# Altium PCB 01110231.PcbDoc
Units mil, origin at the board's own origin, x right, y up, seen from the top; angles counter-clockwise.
Board outline 3350 x 4325 mil, 2 copper layers (Top Layer, Bottom Layer); 144 components, 62 nets, 316 pads, 13 vias.
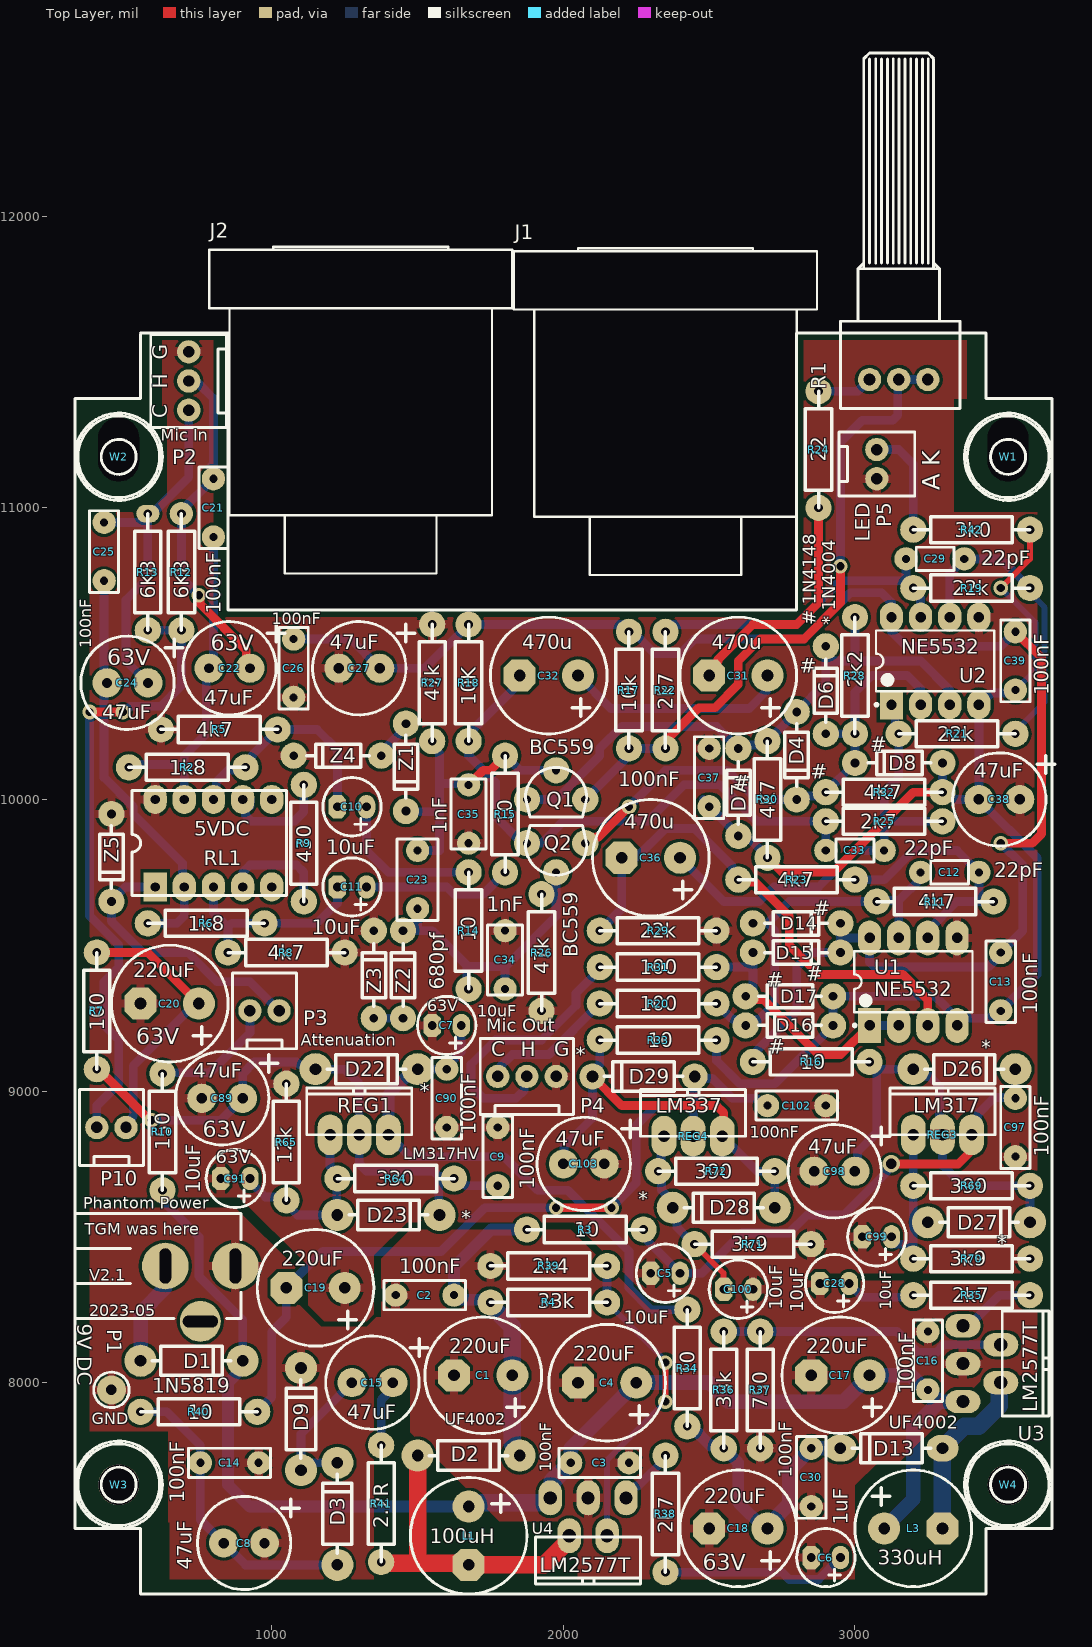
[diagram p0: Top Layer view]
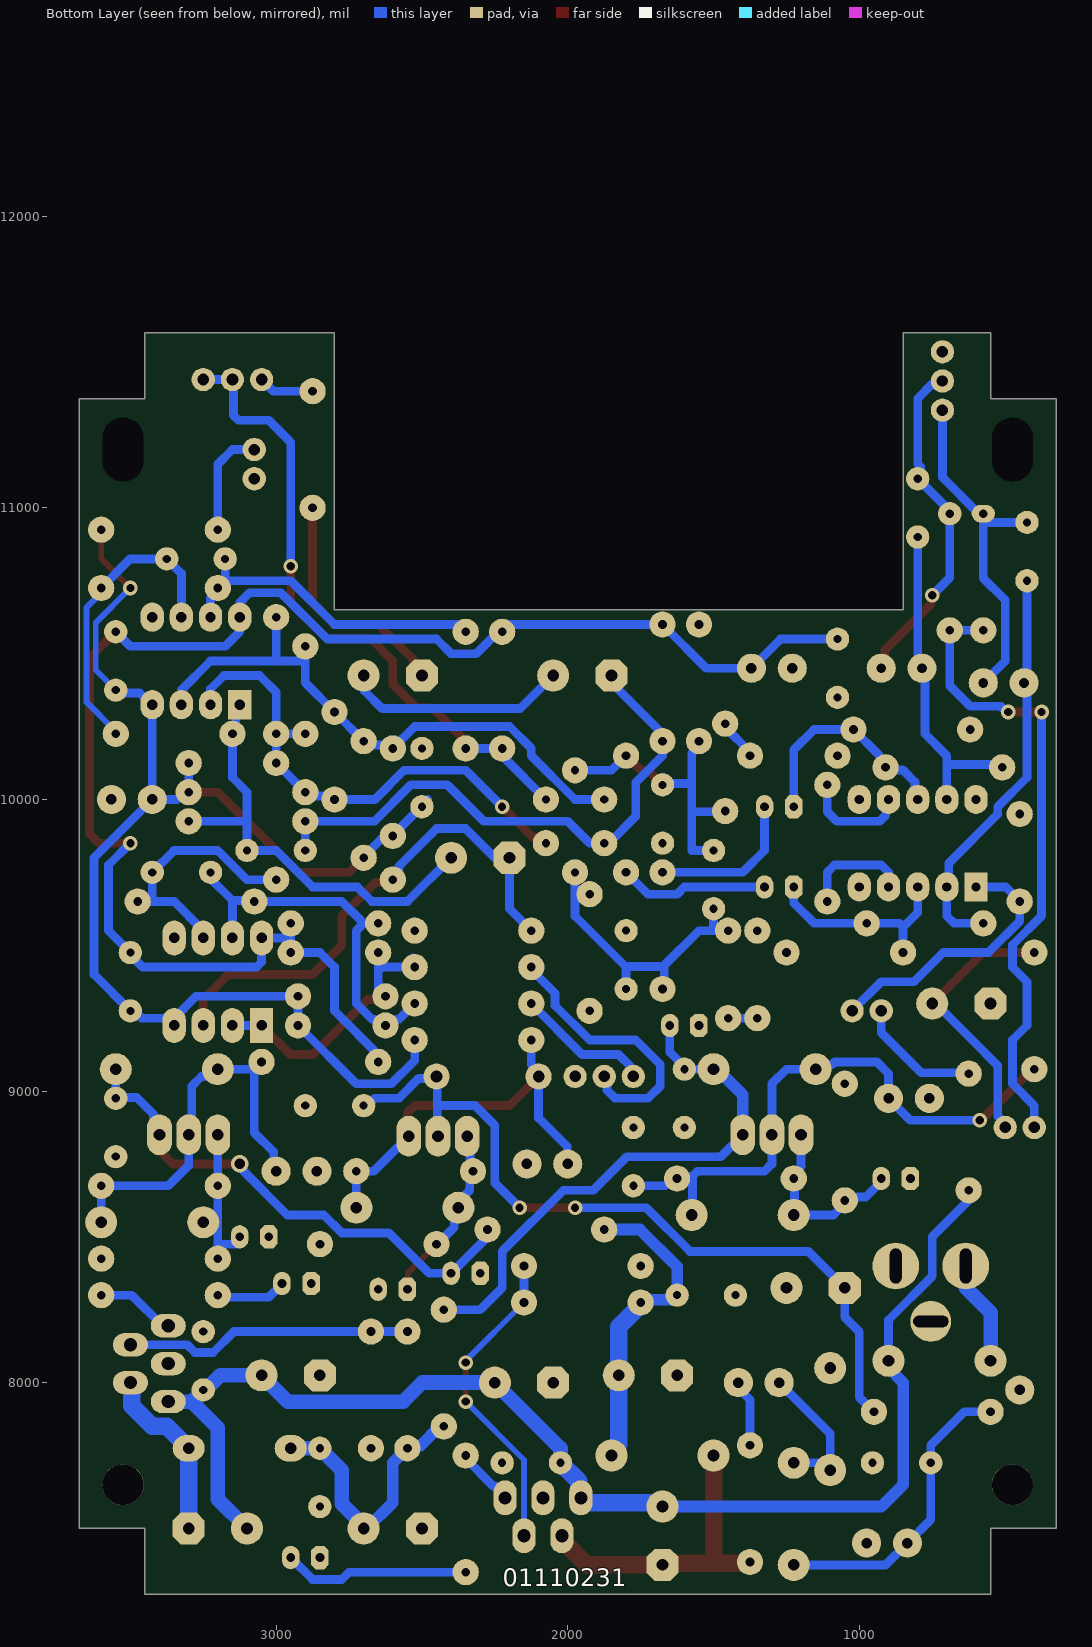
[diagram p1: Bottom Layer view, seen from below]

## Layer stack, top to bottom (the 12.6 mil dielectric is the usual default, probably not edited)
Top Solder: solder mask 0.4, Solder Resist, Dk 3.5
Top Layer: signal copper 1.4
Dielectric1: dielectric 12.6, FR-4, Dk 4.8
Bottom Layer: signal copper 1.4
Bottom Solder: solder mask 0.4, Solder Resist, Dk 3.5

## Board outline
325,7500 550,7500 550,7275 3450,7275 3450,7500 3675,7500 3675,11375 3450,11375 3450,11600 2800,11600 2800,10650 850,10650 850,11600 550,11600 550,11375 325,11375

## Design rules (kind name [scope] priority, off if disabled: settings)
Clearance Clearance_1 [All] p1: gap=10 ignorepadtopadclearanceinfootprint=TRUE
Clearance Clearance_poly [(IsRegion)] p2: gap=10 ignorepadtopadclearanceinfootprint=FALSE
DiffPairsRouting [All] p1: maxlimit=10 minlimit=10 mostfreqgap=10 toplayer_minwidth=15 toplayer_maxwidth=15 toplayer_prefwidth=15 bottomlayer_minwidth=15 bottomlayer_maxwidth=15 bottomlayer_prefwidth=15 substack1={E4759729-C15E-44EF-B839-1660CB1699A4} toplayer_{e4759729-c15e-44ef-b839-1660cb1699a4}_minwidth=15 toplayer_{e4759729-c15e-44ef-b839-1660cb1699a4}_maxwidth=15 toplayer_{e4759729-c15e-44ef-b839-1660cb1699a4}_prefwidth=15 bottomlayer_{e4759729-c15e-44ef-b839-1660cb1699a4}_minwidth=15 bottomlayer_{e4759729-c15e-44ef-b839-1660cb1699a4}_maxwidth=15 bottomlayer_{e4759729-c15e-44ef-b839-1660cb1699a4}_prefwidth=15 substack2={AF7D8FCE-D8A9-40D7-8453-C7F108753530} toplayer_{af7d8fce-d8a9-40d7-8453-c7f108753530}_minwidth=15 toplayer_{af7d8fce-d8a9-40d7-8453-c7f108753530}_maxwidth=15 toplayer_{af7d8fce-d8a9-40d7-8453-c7f108753530}_prefwidth=15 bottomlayer_{af7d8fce-d8a9-40d7-8453-c7f108753530}_minwidth=15 bottomlayer_{af7d8fce-d8a9-40d7-8453-c7f108753530}_maxwidth=15 bottomlayer_{af7d8fce-d8a9-40d7-8453-c7f108753530}_prefwidth=15 maxuncoupledlength=500
Height [All] p1: minheight=0 maxheight=1130 prefheight=500
HoleSize [All] p1: absolutevalues=TRUE maxlimit=400 minlimit=1 maxpercent=80.000 minpercent=20.000
PlaneConnect [All] p1: planeconnectstyle=Relief reliefexpansion=20 reliefentries=4 reliefconductorwidth=30 reliefairgap=10
PolygonConnect [All] p1: connectstyle=Relief reliefconductorwidth=30 reliefentries=4 polygonreliefangle="90 Angle" airgapwidth=10
RoutingVias [All] p1: holewidth=16 width=32 viastyle="Through Hole" minholewidth=8 minwidth=16 maxholewidth=200 maxwidth=200
SilkToSolderMaskClearance SilkscreenOverComponentPads [IsPad] p1: minsilkscreentomaskgap=10 clearancetoexposedcopper=TRUE
SolderMaskExpansion [All] p1: expansion=4 istentingtop=FALSE
Width [All] p1: maxlimit=250 minlimit=10 preferedwidth=40 substack1={E4759729-C15E-44EF-B839-1660CB1699A4} substack2={AF7D8FCE-D8A9-40D7-8453-C7F108753530}
25 further rules are at their usual default settings.

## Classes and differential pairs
component class "Mic Interface": C10 C11 C12 C13 C20 C21 C22 C23 C24 C25 C26 C27 C29 C31 C32 C33 C34 C35 C36 C37 C38 C39 D4 D6 D7 D8 D14 D15 D16 D17 J1 J2 P2 P3 P4 P5 P10 Q1 Q2 R1 R2 R5 R6 R7 R8 R9 R10 R11 R12 R13 R14 R15 R16 R17 R18 R19 R20 R21 R22 R23 R24 R25 R26 R27 R28 R29 R30 R31 R32 R33 R42 RL1 U1 U2 Z1 Z2 Z3 Z4 Z5
component class "Power Supply": C1 C2 C3 C4 C5 C6 C7 C8 C9 C14 C15 C16 C17 C18 C19 C28 C30 C89 C90 C91 C97 C98 C99 C100 C102 C103 D1 D2 D3 D9 D13 D22 D23 D26 D27 D28 D29 F2 L1 L3 L6 P1 R3 R4 R34 R35 R36 R37 R38 R39 R40 R41 R64 R65 R69 R70 R71 R72 REG1 REG3 REG4 U3 U4 W1 W2 W3 W4

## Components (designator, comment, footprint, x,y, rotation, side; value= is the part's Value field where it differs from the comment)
C1 "220uF" RB.2/.4 1825,8025 r0 top
C2 "100nF" AXIAL0.2-2.5mm-CAP 1625,8300 r180 top
C3 "100nF" AXIAL0.2-2.5mm-CAP 2025,7725 r0 top
C4 "220uF" RB.2/.4 2250,8000 r0 top
C5 "10uF" RB.1/.2-PTH 2400,8375 r0 top
C6 "1uF" RB.1/.2-PTH 2950,7400 r0 top
C7 "10uF" RB.1/.2-PTH 1650,9225 r0 top
C8 "47uF" RB3.5/8mm 975,7450 r180 top
C9 "100nF" AXIAL0.2-2.5mm-CAP 1775,8675 r90 top
C10 "10uF" RB.1/.2-PTH 1325,9975 r0 top
C11 "10uF" RB.1/.2-PTH 1325,9700 r0 top
C12 "22pF" AXIAL0.2 3225,9750 r0 top
C13 "100nF" AXIAL0.2-2.5mm-CAP 3500,9475 r270 top
C14 "100nF" AXIAL0.2-2.5mm-CAP 755,7725 r0 top
C15 "47uF" RB3.5/8mm 1415,8000 r180 top
C16 "100nF" AXIAL0.2-2.5mm-CAP 3250,7975 r90 top
C17 "220uF" RB.2/.4 3050,8025 r0 top
C18 "220uF" RB.2/.4 2700,7500 r0 top
C19 "220uF" RB.2/.4 1250,8325 r0 top
C20 "220uF" RB.2/.4 750,9300 r0 top
C21 "100nF" AXIAL0.2-2.5mm-CAP 800,11100 r270 top
C22 "47uF" RB3.5/8MM 925,10450 r180 top
C23 "680pf" AXIAL0.2-3.5mm-CAP 1500,9825 r270 top
C24 "47uF" RB3.5/8MM 575,10400 r180 top
C25 "100nF" AXIAL0.2-2.5mm-CAP 425,10950 r270 top
C26 "100nF" AXIAL0.2-2.5mm-CAP 1075,10550 r270 top
C27 "47uF" RB3.5/8mm 1370,10450 r180 top
C28 "10uF" RB.1/.2-PTH 2980,8340 r0 top
C29 "22pF" AXIAL0.2 3175,10825 r0 top
C30 "100nF" AXIAL0.2-2.5mm-CAP 2850,7775 r270 top
C31 "470u" RB.2/.4 2700,10425 r0 top
C32 "470u" RB.2/.4 2050,10425 r0 top
C33 "22pF" AXIAL0.2 2900,9825 r0 top
C34 "1nF" AXIAL0.2-CAP 1800,9550 r270 top
C35 "1nF" AXIAL0.2-CAP 1675,9850 r90 top
C36 "470u" RB.2/.4 2400,9800 r0 top
C37 "100nF" AXIAL0.2-2.5mm-CAP 2500,10175 r270 top
C38 "47uF" RB3.5/8mm 3565,10000 r180 top
C39 "100nF" AXIAL0.2-2.5mm-CAP 3550,10575 r270 top
C89 "47uF" RB3.5/8mm 900,8975 r180 top
C90 "100nF" AXIAL0.2-2.5mm-CAP 1600,9075 r270 top
C91 "10uF" RB.1/.2-PTH 925,8700 r0 top
C97 "100nF" AXIAL0.2-2.5mm-CAP 3550,8975 r270 top
C98 "47uF" RB3.5/8mm 3000,8725 r180 top
C99 "10uF" RB.1/.2-PTH 3125,8500 r0 top
C100 "10uF" RB.1/.2-PTH 2650,8320 r0 top
C102 "100nF" AXIAL0.2-2.5mm-CAP 2900,8950 r180 top
C103 "47uF" RB3.5/8mm 2140,8750 r180 top
D1 "1N5819" DIODE0.35-TH#1 550,8075 r0 top
D2 "UF4002" DIODE0.35-TH#1 1500,7750 r0 top
D3 "UF4002" DIODE0.35-TH#1 1225,7375 r90 top
D4 "1N914" "DIODE0.3-TH - AK" 2800,10300 r270 top
D6 "1N914" "DIODE0.3-TH - AK" 2900,10225 r90 top
D7 "1N914" "DIODE0.3-TH - AK" 2600,9875 r90 top
D8 "1N914" "DIODE0.3-TH - AK" 3300,10125 r180 top
D9 "UF4002" DIODE0.35-TH#1 1100,7700 r90 top
D13 "UF4002" DIODE0.35-TH#2 3300,7775 r180 top
D14 "1N914" "DIODE0.3-TH - AK" 2650,9575 r0 top
D15 "1N914" "DIODE0.3-TH - AK" 2650,9475 r0 top
D16 "1N914" "DIODE0.3-TH - AK" 2925,9225 r180 top
D17 "1N914" "DIODE0.3-TH - AK" 2925,9325 r180 top
D22 "1N4004" DIODE0.35-TH#1 1150,9075 r0 top
D23 "1N4004" DIODE0.35-TH#1 1225,8575 r0 top
D26 "1N4004" DIODE0.35-TH#1 3200,9075 r0 top
D27 "1N4004" DIODE0.35-TH#1 3250,8550 r0 top
D28 "1N4004" DIODE0.35-TH#1 2725,8600 r180 top
D29 "1N4004" DIODE0.35-TH#3 2450,9050 r180 top
J1 "XLR Panel Socket" "XLR_3 - Altronics P0850" 2350,10600 r0 top
J2 "XLR Panel Plug" "XLR_3 - Altronics P0850" 1305,10605 r0 top
L1 "100uH" RB.2/.4 1675,7575 r90 top
L3 "330uH" RB.2/.4 3100,7500 r180 top
P1 "Power" "2.1MM SOCKET" 875,8400 r180 top
P2 "Mic In" "HEADER 3 SIL" 715,11535 r270 top
P3 "Attenuation" "HEADER 2 SIL" 1025,9275 r180 top
P4 "Mic Out" "HEADER 3 SIL" 1975,9050 r180 top
P5 "LED" "Header 2 SIL" 3075,11100 r90 top
P10 "Phantom Power" "HEADER 2 SIL" 500,8875 r180 top
Q1 "BC559" TO-92BIG 1975,10100 r90 top
Q2 "BC559" TO-92BIG 1975,9750 r270 top
R1 "10K Reverse Log" "POT_Small_Single - TT Single Horizontal" 3150,11440 r180 top
R2 "1k8" AXIAL0.4#1 910,10110 r180 top
R3 "10" AXIAL0.4#1 1875,8525 r0 top
R4 "33k" AXIAL0.4#1 2150,8275 r180 top
R5 "4k7" AXIAL0.4#1 1020,10240 r180 top
R6 "1k8" AXIAL0.4#1 975,9575 r180 top
R7 "100" AXIAL0.4#1 400,9075 r90 top
R8 "4k7" AXIAL0.4#1 850,9475 r0 top
R9 "430" AXIAL0.4#1 1110,10050 r270 top
R10 "150" AXIAL0.4#1 625,9059.69 r270 top
R11 "4k7" AXIAL0.4#1 3075,9650 r0 top
R12 "6K8" AXIAL0.4#2 690,10980 r270 top
R13 "6K8" AXIAL0.4#3 575,10980 r270 top
R14 "10" AXIAL0.4#1 1675,9750 r270 top
R15 "10" AXIAL0.4#1 1800,9750 r90 top
R16 "10" AXIAL0.4#1 3050,9100 r180 top
R17 "10k" AXIAL0.4#1 2225,10175 r90 top
R18 "10K" AXIAL0.4#1 1675,10200 r90 top
R19 "22k" AXIAL0.4#1 3200,10725 r0 top
R20 "100" AXIAL0.4#1 2525,9300 r180 top
R21 "22k" AXIAL0.4#1 3550,10225 r180 top
R22 "2k7" AXIAL0.4#1 2350,10175 r90 top
R23 "4k7" AXIAL0.4#1 3000,9725 r180 top
R24 "22" AXIAL0.4#1 2875,11400 r270 top
R25 "2k7" AXIAL0.4#1 2900,9925 r0 top
R26 "47k" AXIAL0.4#1 1925,9675 r270 top
R27 "47k" AXIAL0.4#1 1550,10200 r90 top
R28 "2k2" AXIAL0.4#1 3000,10625 r270 top
R29 "22k" AXIAL0.4#1 2525,9550 r180 top
R30 "4K7" AXIAL0.4#1 2700,9800 r90 top
R31 "100" AXIAL0.4#1 2525,9425 r180 top
R32 "4K7" AXIAL0.4#1 3300,10025 r180 top
R33 "10" AXIAL0.4#1 2125,9175 r0 top
R34 "10" AXIAL0.4#1 2425,7850 r90 top
R35 "2k7" AXIAL0.4#1 3200,8300 r0 top
R36 "33k" AXIAL0.4#1 2550,8175 r270 top
R37 "750" AXIAL0.4#1 2675,7775 r90 top
R38 "2k7" AXIAL0.4#1 2350,7350 r90 top
R39 "2k4" AXIAL0.4#1 1750,8400 r0 top
R40 "10" AXIAL0.4#1 550,7900 r0 top
R41 "2.2R" AXIAL0.4#1 1375,7385 r90 top
R42 "3k0" AXIAL0.4#1 3200,10925 r0 top
R64 "330" AXIAL0.4#1 1225,8700 r0 top
R65 "12k" AXIAL0.4#1 1050,9025 r270 top
R69 "390" AXIAL0.4#1 3200,8675 r0 top
R70 "3k9" AXIAL0.4#1 3600,8425 r180 top
R71 "3k9" AXIAL0.4#1 2450,8475 r0 top
R72 "390" AXIAL0.4#1 2725,8725 r180 top
REG1 "LM317HV" TO-220-REG 1300,8850 r0 top
REG3 "LM317" TO-220-REG 3300,8850 r0 top
REG4 "LM337" TO-220-REG 2444.99,8845 r0 top
RL1 "5VDC" DIP10 600,9700 r90 top
U1 "NE5532" DIP-8#1 3200,9375 r90 top
U2 "NE5532" DIP-8#2 3275,10475 r90 top
U3 "LM2577T" "TO-220 - 5PIN" 3520,8065 r270 top
U4 "LM2577T" "TO-220 - 5pin" 2085,7455 r180 top
W1 "Washer" "M3 Crinkle" 3525,11175 r0 top
W2 "Washer" "M3 Crinkle" 475,11175 r0 top
W3 "Washer" "M3 Crinkle" 475,7650 r0 top
W4 "Washer" "M3 Crinkle" 3525,7650 r0 top
Z1 "6V8" "DIODE0.3-TH - AK" 1460,10260 r270 top
Z2 "6V8" "DIODE0.3-TH - AK" 1450,9250 r90 top
Z3 "6V8" "DIODE0.3-TH - AK" 1350,9250 r90 top
Z4 "6V8" "DIODE0.3-TH - AK" 1375,10150 r180 top
Z5 "6V8" "DIODE0.3-TH - AK" 450,9950 r270 top

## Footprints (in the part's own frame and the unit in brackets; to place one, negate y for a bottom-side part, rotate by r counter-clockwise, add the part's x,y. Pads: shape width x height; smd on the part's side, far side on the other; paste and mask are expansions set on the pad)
"2.1MM SOCKET" [mil] "Altronics P0620 Socket"
  round 160 hole 40 slot 120 at 90 deg: 1(0,0) 2(240,0)
  round 140 hole 40 slot 120 at 0 deg: 3(120,190)
  silkscreen extent -20,-180 550,180, body extent -25,-185 555,185, height 400
AXIAL0.2 [mil]
  round 80 hole 28: 1(0,0) 2(200,0)
  silkscreen extent 35,-40 165,40, body extent 30,-45 170,45, height 200
AXIAL0.2-2.5mm-CAP [mil]
  round 80 hole 28: 1(0,0) 2(200,0)
  silkscreen extent -40,-50 240,50, body extent -40,-50 240,50, height 200
AXIAL0.2-3.5mm-CAP [mil]
  round 80 hole 28: 1(0,0) 2(200,0)
  silkscreen extent -40,-70 240,70, body extent -40,-70 240,70, height 200
AXIAL0.2-CAP [mil]
  round 80 hole 28: 1(0,0) 2(200,0)
  silkscreen extent -20,-60 220,60, body extent -25,-65 225,65, height 200
AXIAL0.4#1 [mil] "resistor"
  round 90 hole 30: 1(0,0) 2(400,0)
  silkscreen extent 0,-45 400,45, body extent -5,-50 405,50, height 100
AXIAL0.4#2 [mil] "resistor"
  round 80 hole 30: 1(0,0)
  round 90 hole 30: 2(400,0)
  silkscreen extent 0,-45 400,45, body extent -5,-50 405,50, height 100
AXIAL0.4#3 [mil] "resistor"
  oval 60x80 hole 30: 1(0,0)
  round 90 hole 30: 2(400,0)
  silkscreen extent 0,-45 400,45, body extent -5,-50 405,50, height 100
"DIODE0.3-TH - AK" [mil] "DO-35 Footprint"
  round 90 hole 30: A(0,0) K(300,0)
  silkscreen extent 40,-40 255,40, body extent -15,-40 315,40, height 95
DIODE0.35-TH#1 [mil]
  round 110 hole 40: 1(0,0) 2(350,0)
  silkscreen extent 40,-50 310,50, body extent -15,-55 365,55, height 110
DIODE0.35-TH#2 [mil]
  oval 110x90 hole 40: 1(0,0) 2(350,0)
  silkscreen extent 40,-50 310,50, body extent -15,-55 365,55, height 110
DIODE0.35-TH#3 [mil]
  round 90 hole 40: 1(0,0) 2(350,0)
  silkscreen extent 40,-50 310,50, body extent -15,-55 365,55, height 110
DIP10 [mil] "DPDT signal relay"
  rect 100x80 hole 32: 1(0,0)
  oval 100x80 hole 32: 2(0,-100) 3(0,-200) 4(0,-300) 5(0,-400) 6(300,-400) 7(300,-300) 8(300,-200) 9(300,-100) 10(300,0)
  silkscreen extent -30,-450 330,80, body extent -30,-450 330,80, height 300
DIP-8#1 [mil] "DIP; 8 Leads; Row Spacing 7.62 mm; Pitch 2.54 mm"
  rect 120x80 hole 36: 1(-150,150)
  oval 120x80 hole 36: 2(-150,50) 3(-150,-50) 4(-150,-150) 5(150,-150) 6(150,-50) 7(150,50) 8(150,150)
  silkscreen extent -155,-203 104,206, body extent -142,-203 142,203, height 200
DIP-8#2 [mil] "DIP; 8 Leads; Row Spacing 7.62 mm; Pitch 2.54 mm"
  rect 100x80 hole 35.43: 1(-150,150)
  oval 100x80 hole 35.43: 2(-150,50) 3(-150,-50) 4(-150,-150) 5(150,-150) 6(150,-50) 7(150,50) 8(150,150)
  silkscreen extent -155,-203 104,206, body extent -142,-203 142,203, height 200
"HEADER 2 SIL" [mil] "Altronics P5494"
  round 80 hole 39.37: 1(0,0) 2(100,0)
  silkscreen extent -60,-130 160,130, body extent -65,-135 160,135, height 460
"Header 2 SIL" [mil] "Altronics P5494"
  round 80 hole 39.37: 1(0,0) 2(100,0)
  silkscreen extent -60,-130 160,130, body extent -65,-135 160,135, height 460
"HEADER 3 SIL" [mil] "Altronics P5494"
  round 80 hole 39.37: 1(0,0) 2(100,0) 3(200,0)
  silkscreen extent -60,-130 260,130, body extent -65,-135 260,135, height 460
"M3 Crinkle" [mil] "M3 Crinkle Washer"
  silkscreen extent -140,-140 140,140, body extent -140,-140 140,140, height 20
"POT_Small_Single - TT Single Horizontal" [mil] "Bourns PTV111-1 Single Turn Small"
  round 80 hole 40: 1(-100,0) 2(0,0) 3(100,0)
  silkscreen extent -210,-1120 200,100, body extent -210,-1125 200,100, height 500
RB3.5/8mm [mil]
  round 100 hole 36: 1(0,0) 2(140,0)
  silkscreen extent -120,-160 230,160, body extent -90,-160 230,160, height 450
RB3.5/8MM [mil]
  round 100 hole 34: 1(0,0) 2(140,0)
  silkscreen extent -120,-160 230,160, body extent -90,-160 230,160, height 450
RB.1/.2-PTH [mil]
  oval 60x80 hole 30: 1(0,0)
  oct 60x80 hole 30: 2(-100,0)
  silkscreen extent -150,-100 50,100, body extent -150,-100 50,100, height 300
RB.2/.4 [mil]
  round 110 hole 40: 1(0,0)
  oct 110x110 hole 40: 2(-200,0)
  silkscreen extent -300,-200 100,200, body extent -300,-200 100,200, height 1000
TO-92BIG [mil]
  round 90 hole 28: B(0,0) C(-100,100) E(-100,-100)
  silkscreen extent -160,-105 10,105, body extent -160,-110 10,110, height 500
"TO-220 - 5PIN" [mil]
  oval 80x120 hole 45: 1(-130,-150) 2(-65,-20) 3(0,-150) 4(65,-20) 5(130,-150)
  silkscreen extent -180,-15 180,145, body extent -180,-160 180,145, height 950
"TO-220 - 5pin" [mil]
  oval 80x120 hole 45: 1(-130,-150) 2(-65,-20) 3(0,-150) 4(65,-20) 5(130,-150)
  silkscreen extent -180,-15 180,145, body extent -180,-160 180,145, height 950
TO-220-REG [mil]
  oval 85x140 hole 40: 1(-100,0) 2(-0.12,0.2) 3(100,0)
  silkscreen extent -180,0 180,160, body extent -180,0 180,160, height 800
"XLR_3 - Altronics P0850" [mil] "3 Pin XLR Female Connector"
  silkscreen extent -520,170 520,1290, body extent -525,170 526,1280, height 1220

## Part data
C1 C4 C17 C18 C19 C20: library part "CAPACITOR POL", "Altronics p/n R5148"
C2 C3 C9 C13 C14 C16 C21 C25 C26 C30 C37 C39 C90 C97 C102: library part CAP, "Altronics p/n R3025B"
C5 C10 C11 C28 C99 C100: library part CAPACITOR, "Altronics p/n R6067"
C6: library part CAPACITOR, "Altronics p/n R4718"
C7 C91: library part CAPACITOR, "Altronics p/n R4768"
C8 C15 C27 C38 C89 C98 C103: library part "CAPACITOR POL", "Altronics p/n R5108"
C12 C29 C33: library part CAP, "Altronics p/n R2814"
C22 C24: library part CAPACITOR, "Altronics p/n R5108"
C23: library part CAP, "Mouser p/n 810-FA28C0G1H68100"
C31 C32 C36: library part CAPACITOR, "Altronics p/n R5164"
C34 C35: library part CAP, "Altronics p/n R3001B"
D1: library part DIODE_Numbered, "Altronics p/n Z0040"
D2 D3 D9 D13: library part DIODE_Numbered, "Altronics p/n Z0030"
D4 D6 D7 D8 D14 D15 D16 D17: library part DIODE, "Altronics p/n Z0101"
D22 D26: library part DIODE_Numbered, "Altronics p/n Z0109"
D23 D27 D28 D29: library part DIODE, "Altronics p/n Z0109"
J1: library part "XLR_3 Altronics P0850", "Altronics p/n P0850"
J2: library part "XLR_3 Altronics P0850", "Altronics p/n P0852"
L1: library part INDUCTOR, "Altronics p/n L6222"
L3: library part INDUCTOR, "Altronics p/n L6227"
P1: library part "Header 2", "Altronics p/n P0620"
P2 P4: library part "Header 3", "Altronics p/n  P5493 + P5473"
P3 P5 P10: library part CON2, "Altronics p/n  P5492 + P5472"
Q1 Q2: library part PNP, "Altronics p/n Z1057"
R1: library part POT-SINGLE, "Mouser p/n  858-P091NFC25CR10K or 652-PTD9012015FC103"
R2 R6: library part RES2, "Altronics p/n R7564"
R3 R34 R40: library part RES2, "Altronics p/n Z7510"
R4 R36: library part RES2, "Altronics p/n R7594"
R5 R8 R11 R23 R30 R32: library part RES2, "Altronics p/n R7574"
R7: library part RES2, "Altronics p/n Z7534"
R9: library part RES2, "Altronics p/n R7551"
R10: library part RES2, "Altronics p/n R7538"
R12 R13: library part RES2, "Altronics p/n R7778"
R14 R15 R16 R33: library part RES2, "Altronics p/n R7510"
R17 R18: library part RES2, "Altronics p/n R7582"
R19 R21 R29: library part RES2, "Altronics p/n R7590"
R20 R31: library part RES2, "Altronics p/n R7534"
R22 R25 R35 R38: library part RES2, "Altronics p/n R7568"
R24: library part RES2, "Altronics p/n R7518"
R26 R27: library part RES2, "Altronics p/n R7598"
R28: library part RES2, "Altronics p/n R7566"
R37: library part RES2, "Altronics p/n R7555"
R39 R42 R70 R71: library part RES2, "Altronics p/n R7569"
R41: library part RES2, "Altronics p/n Z7014"
R64: library part RES2, "Altronics p/n R7546"
R65: library part RES2, "Altronics p/n R7584"
R69 R72: library part RES2, "Altronics p/n R7548"
REG1: library part LM317, "Altronics p/n Z0545"
REG3: "Altronics p/n Z0545"
REG4: "Altronics p/n Z0562"
RL1: library part RELAY-DPDT_OMRON, "Altronics p/n S4128B"
U1 U2: library part LF353, "Altronics p/n Z2785"
U3 U4: library part LM2577T-ADJ/NOPB, "Jaycar p/n ZV1640", Manufacturer="National Semiconductor", PackageTopMarking=NSUZXYTTE#*LM2577T*-ADJ*P+, PowerWise=N, Supplier Part Number 1=LM2577T-ADJ-ND
W1 W2 W3 W4: "Altronics p/n H3185"
Z1 Z2 Z3 Z4 Z5: library part ZENER2, "Altronics p/n Z0320"

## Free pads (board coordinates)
  round 140 hole 140: 3(475,7650) 3(3525,7650)
  round 120 hole 140 slot 220 at 90 deg: 3(475,11200) 3(3525,11200)
  round 100 hole 36: 4(450,7975)

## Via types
v1: diameter 50, hole 28, Top Layer to Bottom Layer, 12 vias
v2: diameter 60, hole 36, Top Layer to Bottom Layer, 1 vias

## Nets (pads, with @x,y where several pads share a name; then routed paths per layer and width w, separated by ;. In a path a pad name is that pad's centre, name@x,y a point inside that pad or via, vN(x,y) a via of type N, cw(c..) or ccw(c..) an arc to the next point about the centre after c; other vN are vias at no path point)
48V: C9.1 C89.1 D22.1 D23.2 R7.1 R64.2 REG1.2 | length 2077.5
  Top Layer w30: R7.1 406.95,9075 526.96,8955 ; 537.26,8944.7 526.96,8955 ; v1(587.37,8900) 581.95,8900 526.96,8955
  Bottom Layer w30: R7.1 R7.1@412.37,9075 ; v1(587.37,8900) 825,8900 C89.1 900,9059.69 940.31,9100 1084.61,9100 1094.3,9090.31 1134.69,9090.31 D22.1 1250,9075 1299.88,9025.12 REG1.2 1299.88,8750.12 1325,8725 1554.93,8725 1572.5,8707.43 ; D23.2 1572.5,8577.5 1572.5,8707.43 ; C9.1 1666.24,8675 1641.24,8700 R64.2 1617.57,8707.43 1572.5,8707.43
"+DC Prot": C3.1 C4.1 C16.1 C17.1 D1.2 L1.1 L3.1 R10.2 U3.5 U4.5 | length 4532.6
  Bottom Layer w30: R10.2 621.21,8655.9 621.21,8628.79 750,8500 750,8365 900,8215 D1.2 D1.2@900,8050
  Bottom Layer w40: D1.2@900,8050 850,8000 850,7650 925,7575 L1.1 L1.1@1688.39,7588.39 ; U4.5@1938.39,7588.39 U4.5 U4.5@1962.65,7612.65
  Bottom Layer w50: C3.1 2025,7775 C4.1 2250.43,8000.43 2499.57,8000.43 2565,7935 2960,7935 3035,8010 C17.1@3040,8010 ; C17.1 3191.88,8025 3241.88,7975 C16.1 3250,7974.48 3289.48,7935 ; L3.1 3200,7600 3200,7845.52 3289.48,7935 ; U3.5 3289.48,7935
  Bottom Layer w60: L1.1@1688.39,7588.39 U4.5@1938.39,7588.39 ; U4.5@1962.65,7612.65 1962.65,7662.65 C3.1
+V_filt_2: C13.1 C26.1 C27.1 C39.1 D14.K D15.K R16.2 R17.2 R18.2 U1.8 U2.8 | length 5510.6
  Top Layer w30: U2.8 U2.8@3125,10635 ; v1(3500,9850) 3607.57,9850 3640,9882.43 3640,10485 C39.1
  Bottom Layer w30: C26.1 1270,10550 C27.1 ; C27.1@1375,10450 1525,10450 R18.2 2225,10600 2225,10588.39 2313.39,10500 2400,10500 2450,10550 2825,10550 2983.76,10708.76 3091.24,10708.76 3125,10675 U2.8 3125,10575 3175,10525 3500,10525 C39.1 ; R16.2@2637.38,9121.14 2646.14,9121.14 2800,9275 2800,9425 2850,9475 D15.K 2950,9525 ; D14.K 2950,9525 ; U2.8@3146.66,10628.34 U2.8@3150,10625 ; v1(3500,9850) 3575,9775 3575,9550 C13.1 3500,9467.57 3457.43,9425 3067.57,9425 3050,9442.57 U1.8 2950,9525
+VREG: C98.1 D26.1 D27.2 R16.1 R69.2 REG3.2 | length 1385.1
  Bottom Layer w30: C98.1 3008.69,8733.69 3008.69,8790.66 3075,8856.98 R16.1@3075,9075 ; R16.1 R16.1@3075,9075 ; D27.2 R69.2 3370,8675 3300,8745 3300,8850 3289.48,8860.52 3289.48,9016.77 3256.34,9049.91 3246.73,9049.91 3221.65,9075 D26.1 R16.1@3075,9075
-V_filt_2: C13.2 C37.2 C38.2 C39.2 D7.A D8.A D16.A D17.A R30.1 R32.1 R33.2 R42.2 U1.4 U2.4 | length 4629.4
  Top Layer w20: v1(3500,10725) 3600,10825 R42.2
  Top Layer w30: R30.1 2750,9750 2925,9750 3200,10025 R32.1 ; D16.A@2925,9210 D16.A
  Bottom Layer w20: v1(3500,10725) 3618.75,10606.25 3618.75,10443.75 C39.2
  Bottom Layer w30: C37.2@2480,10000 2480,9997.5 2600,9877.5 D7.A 2611.48,9863.52 2640.24,9863.52 2700,9803.76 R30.1 ; R33.2 2525,9104.96 2604.96,9025 2725,9025 D16.A D17.A 3275,9325 3350,9250 U1.4@3350,9226.9 ; D8.A R32.1 3316.24,10025 3341.24,10000 C38.2 ; U1.4 U1.4@3350,9226.9 ; C39.2 3540.43,10365.43 3468.96,10365.43 3428.53,10325 U2.4 C38.2 ; U1.4@3350,9226.9 3373.1,9250 3461.47,9250 3486.47,9275 C13.2 3625,9400 3625,9800 C38.2
-VREG: C103.2 D28.1 D29.2 R33.1 R72.1 REG4.3 | length 1482.9
  Top Layer w30: D29.2 2200,8950 2525,8950 2550,8925 2550,8850.01 REG4.3
  Bottom Layer w30: C103.2 2002.12,8752.12 2002.12,8809.54 2100,8907.43 2100,8950.12 ; 2100.12,8950 2100,8950.12 ; R33.1@2125,9200 R33.1 2125,9091.24 2100,9066.24 D29.2 2100,8950.12 ; REG4.3@2544.99,8880.01 REG4.3 2544.99,8832.38 2570.4,8806.98 2583.01,8806.98 2664.99,8725 R72.1 D28.1
C: C24.1 C25.1 P2.3 R13.1 | length 1218.1
  Bottom Layer w30: C25.1 R13.1@575,10950 ; C24.1 500,10475 500,10683.76 575,10758.76 R13.1@575,10950 ; P2.3@725,11335 715,11325 715,11105 590,10980 R13.1 R13.1@575,10950
GND: C1.2 C2.2 C3.2 C4.2 C5.2 C6.2 C7.2 C8.1 C9.2 C14.2 C16.2 C17.2 C18.2 C19.1 C20.2 C26.2 C27.2 C28.2 C30.2 C34.1 C35.1 C37.1 C38.1 C89.2 C90.2 C91.2 C97.2 C98.2 C99.2 C100.1 C102.1 C103.1 D9.2 P1.1 P2.1 P4.1 P5.1 pad.4 R5.2 R8.2 R26.2 R27.2 R29.1 R37.1 R39.1 R65.1 R70.1 R71.2 RL1.10 U1.5 U2.5 U3.3 U4.3 Z3.K Z4.K Z5.A
H: C21.1 C22.1 P2.2 R12.1 | length 1166.3
  Top Layer w30: v1(750,10700) 753.83,10696.17 753.83,10671.17 912.82,10512.18 912.82,10462.18 C22.1
  Bottom Layer w30: P2.2 724.57,11425.43 749.57,11425.43 800,11375 800,11150 790.43,11140.43 C21.1@790.43,11115.43 ; v1(750,10700) 690,10760 690,10990 C21.1
MIC: C36.2 R23.2 R29.2 U1.3 | length 1777.2
  Top Layer w30: R23.2 2608.64,9716.36 2658.64,9716.36 2775,9600 2775,9500 2875,9400 3163.52,9400 3250,9313.52 U1.3
  Bottom Layer w30: R29.2 2200,9625 C36.2 2250,9800 2350,9900 2450,9900 2578.86,9771.14 2578.86,9762.38 2600,9741.24 R23.2
Mic_Out_C: P4.3 R20.2 | length 468.2
  Bottom Layer w30: P4.3 1784.57,9059.57 1784.57,9084.57 1825,9125 1950,9125 R20.2
Mic_Out_H: P4.2 R31.2 | length 946
  Bottom Layer w30: P4.2 1865.43,9040.43 1865.43,9002.8 1837.63,8975 1725,8975 1683.18,9016.82 1683.18,9091.24 1766.94,9175 1925,9175 2043.5,9293.5 2043.5,9335.25 2125,9416.76 R31.2
NetC1_1: C1.1 C2.1 D2.2 R3.1 R4.2 | length 1102.1
  Bottom Layer w40: R4.2 1740.43,8284.57 1640.43,8284.57 C2.1 1625,8397.55 1752.45,8525 R3.1
  Bottom Layer w60: R4.2 1750,8266.88 1825,8191.88 C1.1 1825,7788.53 1850,7763.53 D2.2
NetC5_1: C5.1 C97.1 D26.2 R3.2 REG3.3 | length 1770.6
  Top Layer w30: v2(3125,8750) 3354.33,8750 3389.48,8785.15 3389.48,8839.48 REG3.3
  Bottom Layer w30: R3.2 2286.48,8513.52 2286.48,8488.52 C5.1 2475,8375 2613.52,8513.52 2775,8513.52 2836.48,8575 2961.47,8575 3110,8723.53 3110,8726.88 3125,8741.88 v2(3125,8750) ; REG3.3 3400,8892.38 3420.62,8913 3420.62,8920.62 3478.02,8978.02 3546.98,8978.02 C97.1 D26.2
NetC6_1: C6.1 R38.1 | length 641.4
  Bottom Layer w30: R38.1 2750,7350 2775,7325 2875,7325 C6.1
NetC7_1: C7.1 C90.1 D22.2 R34.2 REG1.3 | length 1880.9
  Bottom Layer w30: REG1.3 1400,8837.38 1425.41,8811.98 1438.02,8811.98 1475,8775 1797.5,8775 1912.33,8660.17 2014.83,8660.17 2225,8450 2225,8325 2300,8250 R34.2 ; D22.2 C90.1 1600,9083.76 1650,9133.76 C7.1
  Bottom Layer w40: REG1.3 1400,8987.37 1475,9062.37 D22.2@1475,9075
NetC8_2: C8.2 C14.1 D3.1 R40.1 | length 1041.8
  Bottom Layer w30: R40.1 640,7900 754.9,7785.1 754.9,7725.1 C14.1 755,7530 C8.2 910,7375 D3.1
NetC10_1: C10.1 R14.1 | length 531.1
  Bottom Layer w30: C10.1 1325,9825 1400,9750 R14.1
NetC10_2: C10.2 R2.1 R5.1 RL1.8 | length 789.5
  Bottom Layer w30: RL1.8 809.57,10009.57 809.57,10059.57 851.36,10101.36 901.36,10101.36 R2.1 910,10126.24 933.82,10150.05 933.82,10153.46 1020,10239.64 R5.1 1155.1,10240 1225,10170.1 C10.2
NetC11_1: C11.1 R15.1 | length 516.4
  Bottom Layer w30: C11.1 1600,9700 1625,9675 1725,9675 R15.1
NetC11_2: C11.2 R6.1 R8.1 RL1.3 | length 710
  Bottom Layer w30: RL1.3 800,9612.37 850,9562.37 ; R8.1 850,9562.37 ; C11.2 1225,9644.9 1155.1,9575 R6.1 862.63,9575 850,9562.37
NetC12_1: C12.1 D14.A D16.K R11.1 R20.1 U1.7 | length 1344.8
  Bottom Layer w30: R20.1@2525,9325 2536.48,9313.52 2536.48,9288.52 2578.86,9246.14 2587.62,9246.14 2608.76,9225 D16.K ; D16.K@2641.24,9225 2662.38,9246.14 2671.14,9246.14 2725,9300 2725,9550 2700,9575 ; D14.A 2700,9575 ; U1.7 3150,9653.53 ; C12.1 3225,9728.53 3150,9653.53 ; 2700,9575 2775,9650 R11.1 3078.53,9653.53 3150,9653.53
NetC12_2: C12.2 R11.2 R23.1 U1.6 | length 888.9
  Bottom Layer w30: R23.1 3100,9725 3200,9825 3350,9825 C12.2 3425,9650 ; U1.6 3250,9550 3350,9650 3425,9650 ; R11.2 3425,9650
NetC15_1: C15.1 R41.2 | length 231.6
  Bottom Layer w30: R41.2 1375,7941.06 1415,7981.06 C15.1
NetC15_2: C15.2 D3.2 D9.1 | length 522.5
  Bottom Layer w30: D9.1@1075,7725 D9.1@1100,7725 ; D9.1 D9.1@1100,7725 ; D3.2 D9.1@1100,7725 ; C15.2 1100,7825 D9.1@1100,7725
NetC18_1: C18.1 C30.1 D13.2 R34.1 R36.2 | length 937.1
  Bottom Layer w40: R34.1 2438.53,7850 2503.96,7784.57 2540.43,7784.57 2600,7725 2600,7588.39 2688.39,7500 C18.1
  Bottom Layer w50: C18.1 2700,7509.29 2775,7584.29 2775,7700 C30.1 D13.2
NetC19_2: C19.2 C102.2 D29.1 R40.2 REG4.2 | length 2745
  Top Layer w30: v1(1975,8600) v1(2165,8600) ; REG4.2 REG4.2@2447.44,8847.76 ; D29.1@2447.44,9047.44 D29.1
  Bottom Layer w30: R40.2 1000,7950 1000,8174.35 1050,8224.35 C19.2 1175,8450 1580.82,8450 1730.82,8600 v1(1975,8600) ; v1(2165,8600) 2250,8685 2250,8882.43 2317.57,8950 2445.04,8950 2447.44,8947.6 ; REG4.2 REG4.2@2450,8850.32 ; REG4.2@2447.44,8847.76 2447.44,8947.6 ; D29.1@2447.44,9047.44 2447.44,8947.6 ; D29.1 2456.71,9043.29 2510.57,9043.29 2578.86,8975 2661.47,8975 2686.47,8950 C102.2
NetC20_1: C20.1 P10.1 R7.2 | length 958.1
  Top Layer w30: R7.2 575,9475 C20.1
  Bottom Layer w30: P10.1 500,8888.53 525,8913.53 525,9087.12 612.88,9175 737.88,9300 C20.1
NetC21_2: C21.2 C22.2 R2.2 RL1.9 | length 1139.7
  Bottom Layer w30: R2.2 520,10120 700,10120 ; RL1.9 700,10120 ; C22.2@775,10450 800,10475 C21.2 ; C22.2 775,10440 775,10225 700,10150 700,10120
NetC23_1: C23.1 C35.2 Q1.B R15.2 R27.1 Z1.K | length 1095.1
  Top Layer w30: C35.2 1725,10100 1750,10100 R15.2
  Bottom Layer w30: Z1.K 1462.47,9957.53 1575,9957.53 ; C23.1@1475,9825 1563.52,9825 1575,9836.48 ; R27.1 1550,10183.76 1575,10158.76 1575,10054.38 ; 1575,9825 1575,9836.48 ; C35.2@1675,10075 C35.2 1670.62,10054.38 1575,10054.38 ; R15.2 1850,10100 Q1.B ; 1575,9836.48 1575,9957.53 ; 1575,9957.53 1575,10054.38
NetC23_2: C23.2 C34.2 Q2.B R14.2 R26.1 Z2.K | length 1072.7
  Bottom Layer w30: Z2.K@1450,9562.5 Z2.K 1500,9550 ; C23.2 1500,9550 ; R14.2 1668.75,9356.25 1668.75,9426.98 ; C34.2 1800,9426.98 ; R26.1 1975,9675 ; Q2.B@1975,9728.53 1975,9675 ; 1500,9550 1550,9550 1668.75,9431.25 1668.75,9426.98 ; 1668.75,9426.98 1800,9426.98 ; 1800,9426.98 1801.98,9426.98 1975,9600 1975,9675
NetC24_2: C24.2 C25.2 R6.2 RL1.2 | length 1403.4
  Bottom Layer w30: C24.2@425,10425 425,10075 525,9975 525,9950 693.63,9781.37 693.63,9706.37 RL1.2 700,9600 675,9575 R6.2 ; C25.2 425,10435 C24.2@435,10425
NetC28_1: C28.1 R35.1 | length 251.4
  Bottom Layer w30: C28.1 2980,8338.12 3025.62,8292.5 3192.5,8292.5 R35.1 R35.1@3200,8292.5
NetC29_1: C29.1 R19.1 R22.2 U2.7 | length 1132.9
  Bottom Layer w30: R22.2@2350,10600 2800,10600 2950,10750 3175,10750 R19.1 ; R19.1@3175,10741.88 C29.1 ; R19.1@3191.88,10725 3225,10691.88 U2.7 ; U2.7@3240.43,10634.57 U2.7@3250,10625
NetC29_2: C29.2 R19.2 R21.1 U2.6 | length 1049.3
  Bottom Layer w20: R21.1@3550,10233.12 3650,10333.12 3650,10658.76 R19.2@3600,10708.76
  Bottom Layer w30: U2.6 3325,10775 C29.2 3500,10825 R19.2 R19.2@3600,10708.76 ; R21.1 R21.1@3550,10233.12
NetC31_1: C31.1 C32.1 | length 793.8
  Bottom Layer w30: C32.1 2163.52,10311.48 2636.48,10311.48 2696.79,10371.79 C31.1@2696.79,10446.79
NetC31_2: C31.2 R24.2 | length 822.1
  Top Layer w30: C31.2 2500,10443.71 2530.57,10474.28 2530.57,10480.57 2650,10600 2800,10600 2875,10675 R24.2@2875,11003.86
NetC32_2: C32.2 C33.1 Q2.E R18.1 R25.1 | length 1974.5
  Bottom Layer w30: C32.2 1850,10400 1675,10225 R18.1 1675,10150 1766.94,10058.06 1766.94,9941.82 1858.76,9850 Q2.E ; Q2.E@1900,9850 1925,9850 2000,9925 2125,9925 2288.52,9925 2413.52,10050 2537.95,10050 2662.95,9925 R25.1 C33.1
NetC33_2: C33.2 C36.1 R21.2 R25.2 U2.1 | length 1565.7
  Bottom Layer w30: C36.1 2550,9650 2671.47,9650 2721.47,9700 2875,9700 3000,9825 C33.2 3100,9925 ; U2.1 3138.52,10311.48 3138.52,10236.48 R21.2 3150,10075 3100,10025 3100,9925 ; R25.2 3100,9925
NetC91_1: C91.1 D23.1 R64.1 R65.2 REG1.1 | length 644.1
  Bottom Layer w30: C91.1 925,8690 978.52,8636.48 1038.52,8636.48 R65.2 ; R65.2@1046.56,8616.82 1088.38,8575 D23.1@1222.5,8575 ; REG1.1 1200,8741.24 1225,8716.24 R64.1 1222.5,8697.5 D23.1@1222.5,8575 ; D23.1 D23.1@1222.5,8575
NetC99_1: C99.1 D27.1 R69.1 R70.2 REG3.1 | length 550
  Bottom Layer w30: C99.1@3125,8475 3200,8475 ; R70.2 3200,8475 ; REG3.1 R69.1 D27.1@3200,8550 ; D27.1 D27.1@3200,8550 ; 3200,8475 D27.1@3200,8550
NetC100_2: C100.2 D28.2 R71.1 R72.2 REG4.1 | length 623.6
  Top Layer w20: R71.1 2548.64,8376.36 2548.64,8321.36 C100.2
  Bottom Layer w30: REG4.1@2335,8810.78 2335,8735 R72.2 2336.48,8713.52 2336.48,8660.17 2375,8621.65 D28.2 2389.65,8585.35 2389.65,8533.22 2447.87,8475 R71.1 ; REG4.1@2344.99,8810.78 REG4.1
NetD1_1: D1.1 P1.2 | length 285.2
  Bottom Layer w50: D1.1 550,8240 P1.2@635,8325
NetD2_1: D2.1 L1.2 R41.1 U4.4 | length 1069.1
  Top Layer w60: R41.1 1380,7380 1500,7380 ; D2.1 1500,7380 ; U4.4 2020,7460.41 1934.59,7375 L1.2 1670,7380 1500,7380
NetD4_A: D4.A D6.K D7.K Q1.C R28.1 R30.2 U2.3 | length 2058.9
  Bottom Layer w30: Q1.C 1975,10000 2125,10150 2125,10175 2200,10250 2525,10250 D7.K 2611.48,10186.48 2670.24,10186.48 2683.76,10200 R30.2 D4.A 2900,10400 2900,10475 ; D6.K 2900,10475 ; R28.1 3000,10475 ; U2.3 3325,10375 3225,10475 3000,10475 ; 2900,10475 3000,10475
NetD4_K: D4.K D6.A D8.K Q2.C R28.2 R32.2 U2.2 | length 1773
  Top Layer w30: Q2.C 2091.24,9850 2112.38,9871.14 2121.14,9871.14 v1(2225,9975)
  Bottom Layer w30: v1(2225,9975) 2350,10100 2561.48,10100 2662.05,9999.43 2799.43,9999.43 2811.48,10011.48 2870.24,10011.48 2883.76,10025 R32.2 D8.K R28.2 ; D6.A R28.2@2970.24,10225 ; R28.2@2983.76,10225 R28.2 ; U2.2 3225,10378.86 3178.86,10425 3057.43,10425 3000,10367.57 R28.2
NetD13_1: D13.1 L3.2 U3.4 | length 613.2
  Bottom Layer w60: L3.2 D13.1 3301.88,7775 3325,7798.12 3325,7800 3375,7850 3425,7850 3495.58,7920.58 3495.58,7990.76 3500,7995.19 U3.4
NetD15_A: D15.A D17.K R31.1 U1.1 U1.2 | length 964.9
  Top Layer w30: D17.K 2636.48,9313.52 2686.48,9313.52 2699.99,9300.01 2875,9125 2950,9125 U1.1
  Bottom Layer w30: R31.1 2637.5,9425 2650,9412.5 ; R31.1@2525,9450 R31.1@2531.24,9456.24 ; D17.K 2650,9350 2650,9412.5 ; D15.A@2633.76,9475 D15.A 2650,9412.5 ; U1.1 U1.2
NetP3_1: P3.1 RL1.1 Z5.K | length 967
  Bottom Layer w30: RL1.1@625,9700 497.57,9700 450,9652.43 450,9582.47 557.47,9475 712.37,9475 812.37,9375 925,9375 P3.1
NetP3_2: P3.2 R10.1 | length 432
  Bottom Layer w30: R10.1@625,9062.37 787.37,9062.37 925,9200 P3.2
NetP5_2: P5.2 R42.1 | length 370.7
  Bottom Layer w30: P5.2 3150,11200 3200,11150 R42.1
NetP10_2: P10.2 R12.2 R13.2 | length 2196.2
  Top Layer w30: v1(375,10300) v1(489.23,10300)
  Bottom Layer w30: v1(375,10300) 375,9600.9 475,9500.9 475,9425 425,9375 425,9225 475,9175 475,9025 400,8950 P10.2 ; v1(489.23,10300) 494.64,10300 514.64,10320 620,10320 690,10390 R12.2 R13.2
NetQ1_E: Q1.E R1.1 R1.2 R17.1 R22.1 | length 2211.3
  Top Layer w30: R22.1@2350,10200 2464.36,10314.36 2519.83,10314.36 2600,10394.53 2600,10475 2675,10550 2825,10550 2950,10675 v1(2950,10800)
  Bottom Layer w30: Q1.E 2216.36,10141.36 R17.1@2216.36,10175 ; R17.1 R22.1 ; v1(2950,10800) 2950,11225 3025,11300 3129.08,11300 3146.66,11317.57 3146.66,11436.66 R1.2 ; R1.2@3150,11439.9 3249.9,11439.9 R1.1
NetR1_3: R1.3 R24.1 | length 191.6
  Bottom Layer w30: R24.1 3010,11400 R1.3
NetR4_1: R4.1 R39.2 U4.2 | length 1090.7
  Top Layer w20: v1(2350,7935) v1(2350,8068.75)
  Bottom Layer w20: U4.2 2150,7735 v1(2350,7935) ; R4.1 v1@2350,8075
  Bottom Layer w30: R4.1 R39.2 ; v1(2350,8068.75) v1@2350,8075
NetR9_1: R9.1 RL1.7 | length 396.7
  Bottom Layer w30: RL1.7 909.57,9990.43 909.57,9945.79 930.36,9925 1077.47,9925 1110,9957.53 R9.1 ; RL1.7@925,9976.47 RL1.7@925,10000
NetR9_2: R9.2 RL1.4 | length 380.7
  Bottom Layer w30: RL1.4 900,9750 925,9775 1085,9775 1110,9750 R9.2
NetR35_2: R35.2 U3.1 | length 280.6
  Bottom Layer w30: U3.1@3375,8200 U3.1 3390,8195 3495,8300 R35.2
NetR36_1: R36.1 R37.2 U3.2 | length 990.6
  Bottom Layer w30: R36.1 R37.2 3145,8175 3216.47,8103.53 3278.53,8103.53 3305,8130 U3.2
NetR38_2: R38.2 U4.1 | length 204.7
  Bottom Layer w30: U4.1 2215,7611.47 2248.63,7645.1 2255.1,7645.1 2350,7740 R38.2
NetZ1_A: Z1.A Z4.A | length 145.2
  Bottom Layer w30: Z4.A 1375,10162.5 1460,10247.5 Z1.A
NetZ2_A: Z2.A Z3.A | length 100
  Bottom Layer w30: Z3.A Z2.A
pads on no net: P1.3 RL1.5 RL1.6

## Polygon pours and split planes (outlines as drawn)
GND on Top Layer "GND_L01_P000" (solid, pour order 0): 375,11325 600,11325 600,11575 3400,11575 3400,11325 3625,11325 3625,7325 375,7325

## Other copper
Top Layer:
  pour cut-out: 3650,8025 3450,8025 3150,7725 3077.5,7725 3000,7647.5 3000,7300 3650,7300
  pour cut-out: 1350,7300 1350,7325 1350,8000 1475,8000 1475,7829.93 1779.93,7525 2042.65,7525 2050,7517.65 2050,7325 2075,7300
  pour cut-out: 338.64,8600 343.48,8636.48 888.52,8636.48 1125,8400 1125,8265 1180,8210 1325,8210 1350,8235 1350,8436.24 1463.76,8550 2035,8550 2310,8275 2456.71,8275 2456.71,8250 2300,8250 2025,8525 1475.41,8525 1375,8424.59 1375,8224.35 1357.47,8224.35 1325,8191.88 1169.3,8191.88 1094.3,8266.88 1094.3,8380.7 875,8600
  pour cut-out: 333.89,11346.57 333.89,11027.74 375.96,10985.66 581.99,10985.66 641.96,11045.63 641.96,11350 337.31,11350
  pour cut-out: 2825,10625 2825,11600 800,11600 800,10625
  pour cut-out: 3677.5,7273.75 3675,7276.25 3675,7523.75 3375,7523.75 3375,7273.75
  pour cut-out: 650,7271.57 650,7521.57 333.89,7521.57 333.89,7271.57
  pour cut-out: 625.13,11346.57 625.13,11596.57 333.89,11596.57 333.89,11346.57
  pour cut-out: 3675,11350 3672.5,11352.5 3672.5,11600 3382.69,11600 3382.69,11350
  pour cut-out: 2837.5,8375 3675,8375 3675,8350 2837.5,8350
  pour cut-out: 3339.34,11375 3672.5,11375 3672.5,10985.64 3339.34,10985.64
  pour cut-out: 645,7507.5 645,7832.5 334.5,7832.5 334.5,7507.5
  pour cut-out: 3690,7325 3690,7822.26 3350,7822.26 3350,7325
Bottom Layer:
  pour cut-out: 2837.5,8350 3675,8350 3675,8375 2837.5,8375
  pour cut-out: 325,11375 650,11375 650,11000 325,11000
  pour cut-out: 3300,11375 3647.5,11375 3647.5,11000 3300,11000
  pour cut-out: 2040,8400 2043.5,8403.5
  pour cut-out: 650,7500 650,7840 332,7840 332,7500
  pour cut-out: 3686.25,7470 3686.25,7825 3350,7825 3350,7470

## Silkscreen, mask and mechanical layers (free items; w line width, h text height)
Top Overlay:
  circle w10: c450,7975 r60.83
  circle w10: c3525,11175 r150
  circle w10: c475,11175 r150
  circle w10: c475,7650 r150
  circle w10: c3525,7650 r150
  lines w10: 550,11595 550,11375 325,11375 325,7500 550,7500 550,7275 3450,7275 3450,7500 3675,7500 3675,11375 3450,11375 3450,11600 2800,11600 2800,10650 850,10650 850,11600 550,11600
  text "G" at 642,11508 h50 r90
  text "H" at 642,11408 h50 r90
  text "C" at 642,11308 h50 r90
  text "A K" at 3290,11060 h60 r90
  text "# 1N4148" at 2865,10598 h45 r90
  text "* 1N4004" at 2932,10598 h45 r90
  text "63V" at 790.43,10510.72 h55
  text "63V" at 435.43,10460.72 h55
  text "#" at 2811.39,10435.05 h50
  text "#" at 3053.14,10165.05 h50
  text "#" at 2848,10071.35 h50
  text "#" at 2583,10033 h50
  text "#" at 2858,9603 h50
  text "#" at 2833,9378 h50
  text "#" at 2698,9358 h50
  text "63V" at 1533,9273 h40
  text "63V" at 535.43,9160.72 h55
  text "#" at 2701.77,9128.01 h50
  text "*" at 3433,9124.67 h50
  text "C" at 1752.19,9118.88 h50
  text "H" at 1853,9118.88 h50
  text "G" at 1968,9118.88 h50
  text "*" at 2043,9099.67 h50
  text "*" at 1507.35,8974.67 h50
  text "63V" at 763,8841.67 h55
  text "63V" at 808,8753 h45
  text "*" at 2256.52,8604.06 h50
  text "*" at 1649.24,8540.41 h50
  text "TGM was here" at 358,8508 h40
  text "*" at 3488,8454.67 h50
  text "V2.1" at 374,8349 h40
  text "2023-05" at 374,8227 h40
  text "9V DC" at 333,8202 h50 r270
  text "GND" at 383,7858 h40
  text "63V" at 2478,7356.01 h55
Bottom Overlay:
  text "01110231" at 2223,7301 h60
Mechanical 15:
  the board outline again, w10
